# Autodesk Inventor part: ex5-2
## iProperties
Shininess: 64.0
Length Units: 11272
Angle Units: 11279
Time Units: 11290
Mass Units: 11286
Length Display Precision: 3
Angle Display Precision: 2
Compacted: True
Part Number: ex5-2
Document SubType Name: Modeling
Created: 2003-11
Designer: Elise Moss
Cost Center: 0.1 lbmass
Authority: 2.15 in^3
Manufacturer: Standard
Standards Organization: Custom
Density: 0.0
Volumn: 0.0
Area: 0.0
PropertySet Name: Model Information
Control State: 0
Master: False
Checked Out: False
SaveDate: 2003-11-13
SaveTime: 14:21
TotalMass: 0.1 lbmass
TotalVolume: 2.15 in^3
Author: Elise Moss
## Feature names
1. Revolution1
2. Hole1
